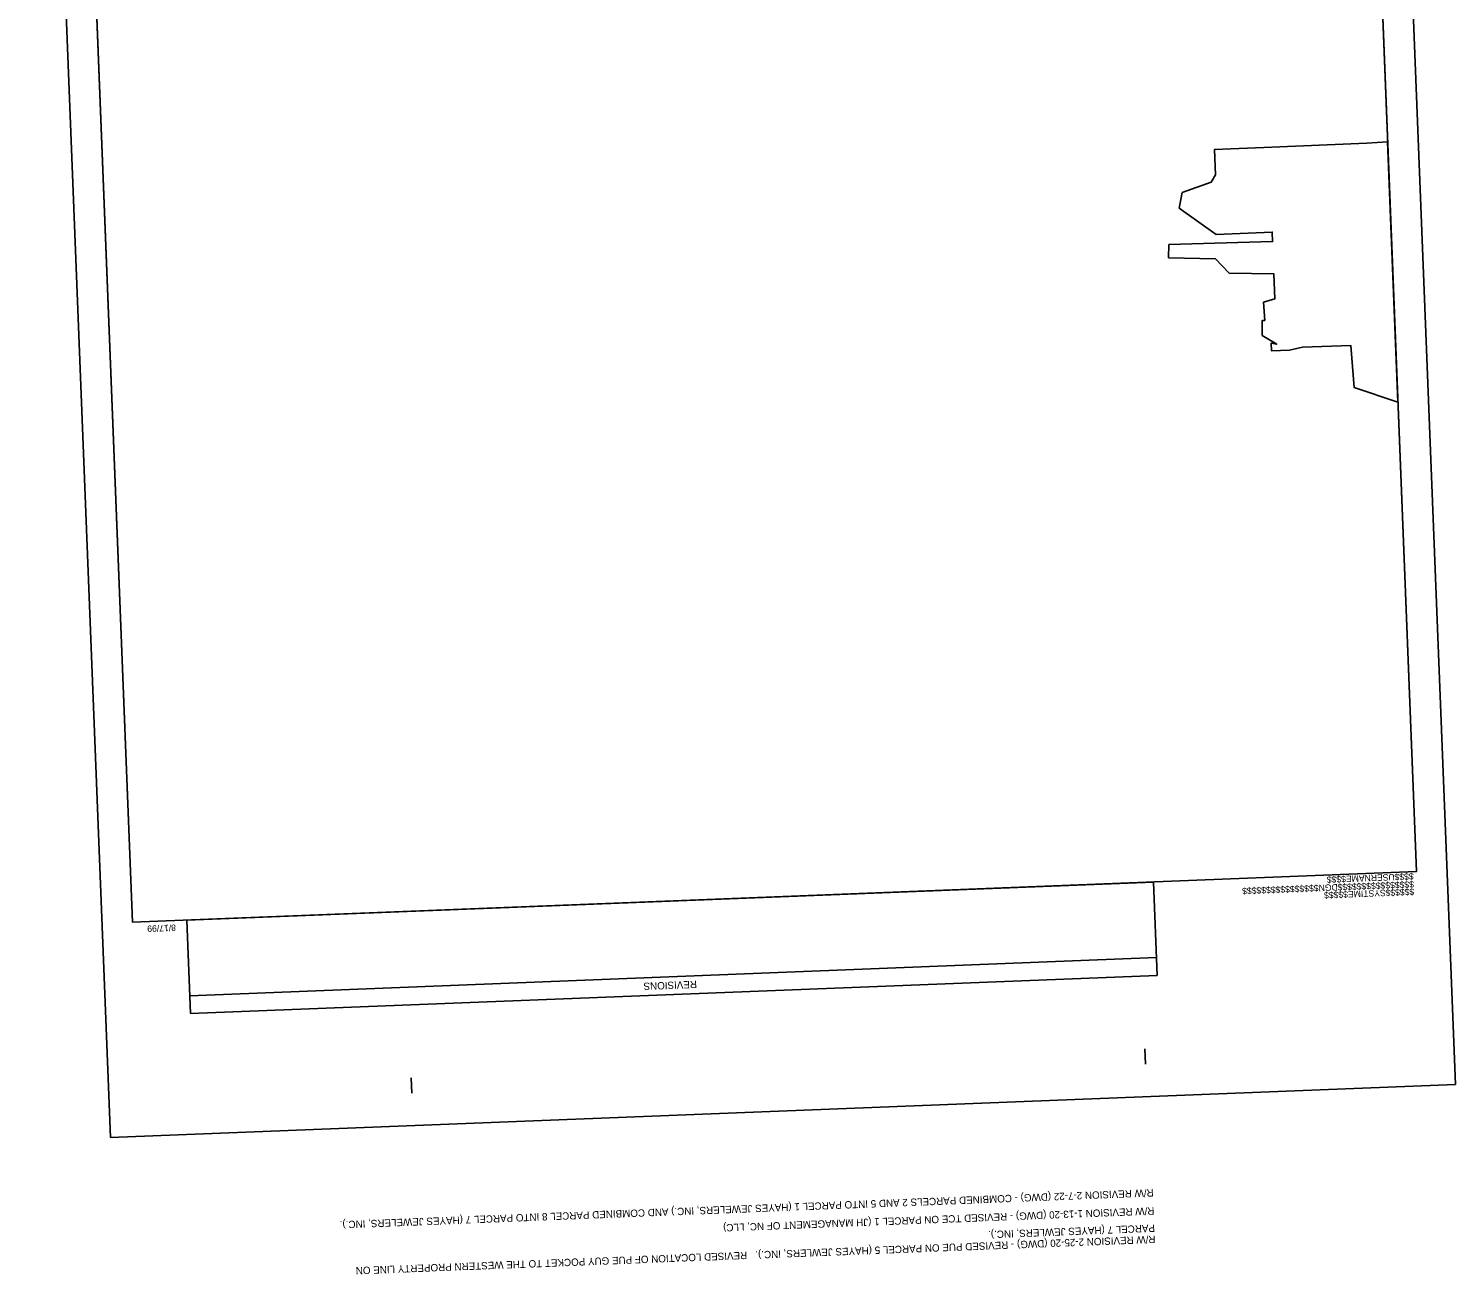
# Model space of a CAD drawing. Extents: x 1627905 to 1629071, y 761064 to 763101.
# Drawn here: x 1627905 to 1629071, y 761064 to 762083 of the extents above; entities that cross this region are included whole.
import ezdxf

# ---------------------------------------------------------------- set-up
doc = ezdxf.new("R2010")
doc.units = 0
for name, color, linetype in [('Prop DSN Text', 7, 'Continuous'), ('Scratch_Level_1', 7, 'Continuous'), ('Sheet Block Revision CELL', 7, 'Continuous'), ('Sheet Block System Information CELL', 7, 'Continuous'), ('Sheet Clip Boundary CELL', 7, 'Continuous'), ('Sheet Plan And Profile CELL', 7, 'Continuous'), ('Sheet Plot Border Outside CELL', 7, 'Continuous')]:
    doc.layers.add(name, color=color, linetype=linetype)

msp = doc.modelspace()

# ---------------------------------------------------------------- linework, layer by layer
at = {"layer": 'Scratch_Level_1'}
msp.add_lwpolyline([(1629024.3, 761777.2), (1628988.5, 761789.4), (1628985.7, 761823.7), (1628946.4, 761822.2), (1628935.6, 761819.9), (1628921.1, 761819.2), (1628920.7, 761825.6), (1628925.2, 761824.7), (1628913.4, 761831.9), (1628913.4, 761844.2), (1628915.5, 761844.2), (1628914.5, 761859), (1628923.7, 761861.9), (1628922.9, 761882.1), (1628886.5, 761882.8), (1628875.1, 761894.4), (1628836.9, 761895.4), (1628837.1, 761906.1), (1628921.9, 761908.6), (1628921.6, 761916.3), (1628875.8, 761914.5), (1628845.5, 761935.9), (1628848, 761948.6), (1628871.7, 761957.1), (1628875.1, 761963), (1628874.3, 761983.8), (1628914.8, 761985.4), (1628998.9, 761989), (1629015.9, 761990)], close=True, dxfattribs=at)
at = {"layer": 'Sheet Block Revision CELL'}
msp.add_line((1628827, 761323.3), (1628037, 761292.2), dxfattribs=at)
msp.add_lwpolyline([(1628827.6, 761308.8), (1628037.6, 761277.7), (1628034.6, 761354), (1628824.6, 761385.1)], close=True, dxfattribs=at)
at = {"layer": 'Sheet Block System Information CELL'}
msp.add_line((1629039.4, 761393.6), (1629039.4, 761393.6), dxfattribs=at)
at = {"layer": 'Sheet Clip Boundary CELL'}
msp.add_lwpolyline([(1628129, 762651.6), (1628122.7, 762811.7), (1628982.2, 762845.6), (1629039.4, 761393.6), (1627990.2, 761352.2), (1627946.9, 762451.3), (1628013.5, 762453.9), (1628005.9, 762646.7)], close=True, dxfattribs=at)
at = {"layer": 'Sheet Plan And Profile CELL'}
for p, q in [((1629039.4, 761393.6), (1629039.4, 761393.6)), ((1629039.4, 761393.6), (1629039.4, 761393.6)), ((1629039.4, 761393.6), (1629039.4, 761393.6)), ((1629039.4, 761393.6), (1629039.4, 761393.6)), ((1629039.4, 761393.6), (1629039.4, 761393.6)), ((1628818, 761236.3), (1628817.5, 761248.7)), ((1628218.4, 761212.6), (1628217.9, 761225.1))]:
    msp.add_line(p, q, dxfattribs=at)
msp.add_lwpolyline([(1627931.1, 762851.1), (1627990.2, 761352.2), (1629039.4, 761393.6), (1628980.3, 762892.4)], close=True, dxfattribs=at)
at = {"layer": 'Sheet Plot Border Outside CELL'}
msp.add_lwpolyline([(1629071.3, 761219.7), (1629004.3, 762918.4), (1627905.2, 762875.1), (1627972.2, 761176.4)], close=True, dxfattribs=at)

# ---------------------------------------------------------------- texts
at = {"layer": 'Prop DSN Text'}
for s, p in [('R/W REVISION 2-7-22 (DWG) - COMBINED PARCELS 2 AND 5 INTO PARCEL 1 (HAYES JEWELERS, INC.) AND COMBINED PARCEL 8 INTO PARCEL 7 (HAYES JEWELERS, INC.).', (1628824.5, 761134.1)), ('R/W REVISION 1-13-20 (DWG) - REVISED TCE ON PARCEL 1 (JH MANAGEMENT OF NC, LLC)', (1628825.1, 761119.3)), ('PARCEL 7 (HAYES JEWLERS, INC.).', (1628825.6, 761105.2)), ('R/W REVISION 2-25-20 (DWG) - REVISED PUE ON PARCEL 5 (HAYES JEWLERS, INC.).   REVISED LOCATION OF PUE GUY POCKET TO THE WESTERN PROPERTY LINE ON ', (1628826, 761096.1))]:
    msp.add_text(s, height=6, rotation=182.2582, dxfattribs=at).set_placement(p)
at = {"layer": 'Sheet Block Revision CELL'}
msp.add_text('REVISIONS', height=6, rotation=182.2582, dxfattribs=at).set_placement((1628451.3, 761304.5))
at = {"layer": 'Sheet Block System Information CELL'}
for s, p in [('$$$$USERNAME$$$$', (1629037.1, 761392.4)), ('$$$$$$$$$$$$$$$$DGN$$$$$$$$$$$$$$$$', (1629037.4, 761385.9)), ('$$$$$$SYSTIME$$$$$', (1629037.6, 761379.8))]:
    msp.add_text(s, height=5.25, rotation=182.2582, dxfattribs=at).set_placement(p)
at = {"layer": 'Sheet Plan And Profile CELL'}
msp.add_text('8/17/99', height=5.25, rotation=182.2582, dxfattribs=at).set_placement((1628025.5, 761350.4))

doc.saveas('drawing.dxf')
